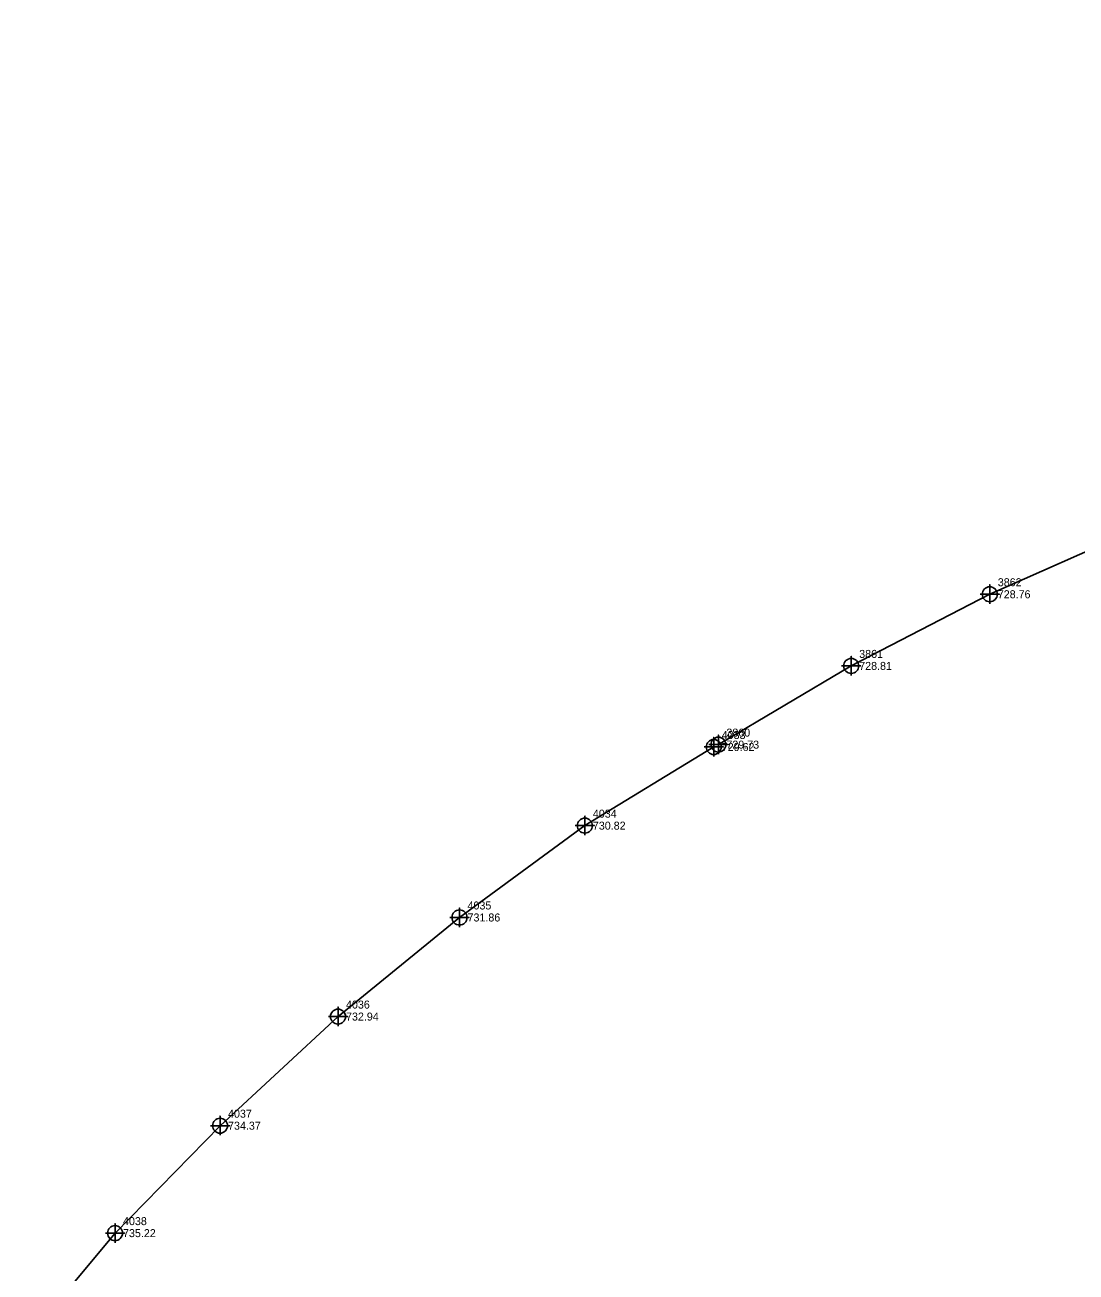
# Model space of a CAD drawing. Extents: x 1622486 to 1624761, y 758733 to 760816.
# Drawn here: x 1623309.4 to 1623637.7, y 759667.2 to 760056.8 of the extents above; entities that cross this region are included whole.
import ezdxf

# ---------------------------------------------------------------- set-up
doc = ezdxf.new("R2010")
doc.units = 0
for name, color, linetype in [('Exist Utilities Gas UG Line SUE', 7, 'Continuous'), ('Exist Utilities Gas UG Line SUE Cogo Elevation', 7, 'Continuous'), ('Exist Utilities Gas UG Line SUE Cogo Number', 7, 'Continuous'), ('Exist Utilities Gas UG Line SUE Cogo Point CELL', 7, 'Continuous')]:
    doc.layers.add(name, color=color, linetype=linetype)

msp = doc.modelspace()

# ---------------------------------------------------------------- linework, layer by layer
at = {"layer": 'Exist Utilities Gas UG Line SUE'}
for points in [[(1623526, 759831.96), (1623567.48, 759856.55), (1623610.76, 759878.94), (1623655.07, 759898.59), (1623701.03, 759919.48), (1623744.33, 759939.8), (1623791, 759959.85), (1623836.2, 759978.89), (1623878.8, 759995.14), (1623920.16, 760009.52), (1623963.56, 760020.82), (1624009.71, 760029.98), (1624054.96, 760035.68), (1624106.85, 760041.87), (1624164.13, 760053.39), (1624209.29, 760056.8), (1624221.97, 760056.55), (1624280.33, 760056.28), (1624310.83, 760055.98), (1624347.04, 760055.47), (1624394.66, 760052.45), (1624442.78, 760047.24), (1624444.88, 760047.16)], [(1623524.55, 759831.22), (1623484.3, 759806.65), (1623445.16, 759777.96), (1623407.21, 759747), (1623370.37, 759712.91), (1623337.57, 759679.35), (1623309.44, 759645.45)]]:
    msp.add_lwpolyline(points, dxfattribs=at)
at = {"layer": 'Exist Utilities Gas UG Line SUE Cogo Point CELL'}
for points in [[(1623607.76, 759878.94), (1623613.76, 759878.94), (1623610.76, 759878.94), (1623610.76, 759881.94), (1623610.76, 759875.94)], [(1623564.48, 759856.55), (1623570.48, 759856.55), (1623567.48, 759856.55), (1623567.48, 759859.55), (1623567.48, 759853.55)], [(1623521.55, 759831.22), (1623527.55, 759831.22), (1623524.55, 759831.22), (1623524.55, 759834.22), (1623524.55, 759828.22)], [(1623523, 759831.96), (1623529, 759831.96), (1623526, 759831.96), (1623526, 759834.96), (1623526, 759828.96)], [(1623481.3, 759806.65), (1623487.3, 759806.65), (1623484.3, 759806.65), (1623484.3, 759809.65), (1623484.3, 759803.65)], [(1623442.16, 759777.96), (1623448.16, 759777.96), (1623445.16, 759777.96), (1623445.16, 759780.96), (1623445.16, 759774.96)], [(1623404.21, 759747), (1623410.21, 759747), (1623407.21, 759747), (1623407.21, 759750), (1623407.21, 759744)], [(1623367.37, 759712.91), (1623373.37, 759712.91), (1623370.37, 759712.91), (1623370.37, 759715.91), (1623370.37, 759709.91)], [(1623334.57, 759679.35), (1623340.57, 759679.35), (1623337.57, 759679.35), (1623337.57, 759682.35), (1623337.57, 759676.35)]]:
    msp.add_lwpolyline(points, dxfattribs=at)
for centre in [(1623610.76, 759878.94), (1623567.48, 759856.55), (1623524.55, 759831.22), (1623526, 759831.96), (1623484.3, 759806.65), (1623445.16, 759777.96), (1623407.21, 759747), (1623370.37, 759712.91), (1623337.57, 759679.35)]:
    msp.add_circle(centre, 2.34, dxfattribs=at)

# ---------------------------------------------------------------- texts
at = {"layer": 'Exist Utilities Gas UG Line SUE Cogo Elevation'}
for s, p in [('728.76', (1623613.26, 759877.69)), ('728.81', (1623569.98, 759855.3)), ('729.62', (1623527.05, 759829.97)), ('729.73', (1623528.5, 759830.71)), ('730.82', (1623486.8, 759805.4)), ('731.86', (1623447.66, 759776.71)), ('732.94', (1623409.71, 759745.75)), ('734.37', (1623372.87, 759711.66)), ('735.22', (1623340.07, 759678.1))]:
    msp.add_text(s, height=2.5, dxfattribs=at).set_placement(p)
at = {"layer": 'Exist Utilities Gas UG Line SUE Cogo Number'}
for s, p in [('3862', (1623613.26, 759881.44)), ('3861', (1623569.98, 759859.05)), ('4033', (1623527.05, 759833.72)), ('3860', (1623528.5, 759834.46)), ('4034', (1623486.8, 759809.15)), ('4035', (1623447.66, 759780.46)), ('4036', (1623409.71, 759749.5)), ('4037', (1623372.87, 759715.41)), ('4038', (1623340.07, 759681.85))]:
    msp.add_text(s, height=2.5, dxfattribs=at).set_placement(p)

doc.saveas('drawing.dxf')
